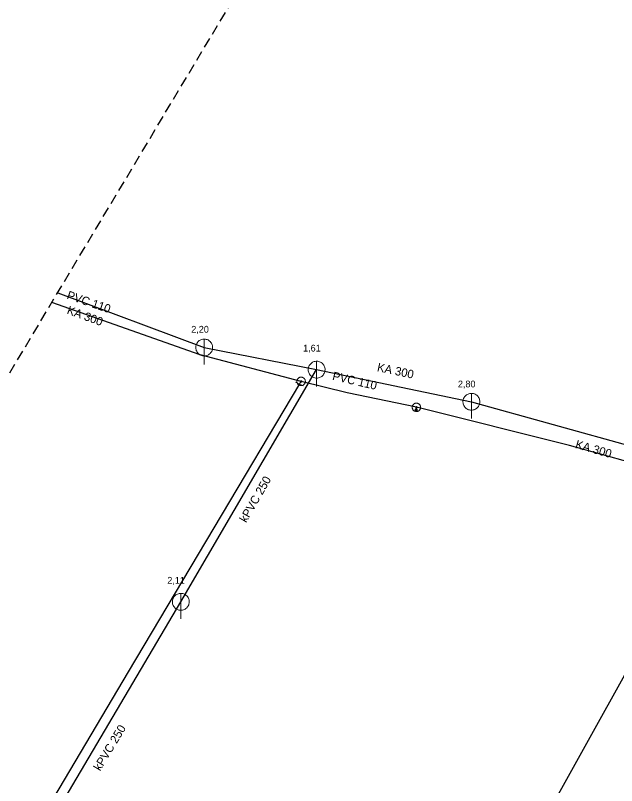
# Model space of a CAD drawing. Extents: x -724358 to -723714, y -973310 to -972026.
# Drawn here: x -724260.8 to -724189.5, y -973035.2 to -972943.8 of the extents above; entities that cross this region are included whole.
import ezdxf

# ---------------------------------------------------------------- set-up
doc = ezdxf.new("R2010")
doc.units = 0
doc.header["$LTSCALE"] = 0.4
doc.linetypes.add('MEDIUM_DASHED', pattern=[4.5, 3, -1.5])
for name, color, linetype, lineweight in [('1', 7, 'Continuous', 13), ('14', 7, 'Continuous', 13), ('17', 7, 'Continuous', 25), ('22', 7, 'Continuous', 13), ('34', 7, 'Continuous', 13), ('47', 7, 'Continuous', 13), ('9', 7, 'Continuous', 13)]:
    doc.layers.add(name, color=color, linetype=linetype, lineweight=lineweight)

msp = doc.modelspace()

# ---------------------------------------------------------------- linework, layer by layer
at = {"layer": '1', "linetype": 'MEDIUM_DASHED', "lineweight": 25}
msp.add_lwpolyline([(-723809.944, -972026.35), (-723713.647, -972034.723), (-723734.581, -972361.295), (-724123.956, -973039.561), (-724241.187, -973309.611), (-724358.418, -973148.418), (-723860.186, -972315.24)], close=True, dxfattribs=at)
at = {"layer": '14', "lineweight": 25}
for p, q in [((-724255.737, -972976.708), (-724238.37, -972983.21)), ((-724206.69, -972989.649), (-724175.35, -972998.37))]:
    msp.add_line(p, q, dxfattribs=at)
at = {"layer": '14'}
for p, q in [((-724226.875, -972987.23), (-724227.079, -972987.531)), ((-724213.21, -972990.309), (-724213.23, -972990.6))]:
    msp.add_line(p, q, dxfattribs=at)
at = {"layer": '14', "lineweight": 25}
for points in [[(-724199.68, -973042.18), (-724175.35, -972998.37), (-724168.649, -972968.05), (-724140.149, -972952.289), (-724129.112, -972956.537), (-724090.03, -972946.64), (-724084.339, -972950.81)], [(-724238.37, -972983.21), (-724225.039, -972985.84), (-724206.69, -972989.649)], [(-724259.629, -973044.75), (-724241.14, -973013.379), (-724225.039, -972985.84)]]:
    msp.add_lwpolyline(points, dxfattribs=at)
at = {"layer": '17'}
for points in [[(-724226.875, -972987.23), (-724238.85, -972984.07), (-724256.424, -972977.857)], [(-724213.21, -972990.309), (-724221.42, -972988.57), (-724226.875, -972987.23)], [(-724227.079, -972987.531), (-724247.38, -973021.691), (-724261.945, -973046.239), (-724298.824, -973108.59), (-724301.364, -973112.34), (-724301.535, -973112.48)], [(-724170.289, -973002.559), (-724176.69, -972999.98), (-724195.07, -972994.829), (-724213.21, -972990.309)]]:
    msp.add_lwpolyline(points, dxfattribs=at)
at = {"layer": '22'}
for p, q in [((-724238.37, -972985.21), (-724238.369, -972982.21)), ((-724225.039, -972987.84), (-724225.038, -972984.84)), ((-724206.69, -972991.649), (-724206.689, -972988.649)), ((-724241.14, -973015.379), (-724241.139, -973012.379))]:
    msp.add_line(p, q, dxfattribs=at)
for points in [[(-724237.37, -972983.21), (-724237.375, -972983.101), (-724237.393, -972982.993), (-724237.423, -972982.887), (-724237.463, -972982.786), (-724237.515, -972982.689), (-724237.577, -972982.599), (-724237.649, -972982.516), (-724237.729, -972982.442), (-724237.817, -972982.376), (-724237.911, -972982.321), (-724238.011, -972982.276), (-724238.116, -972982.243), (-724238.223, -972982.221), (-724238.332, -972982.211), (-724238.442, -972982.213), (-724238.55, -972982.227), (-724238.657, -972982.252), (-724238.76, -972982.289), (-724238.858, -972982.338), (-724238.95, -972982.396), (-724239.036, -972982.465), (-724239.113, -972982.542), (-724239.182, -972982.628), (-724239.241, -972982.72), (-724239.289, -972982.818), (-724239.326, -972982.921), (-724239.352, -972983.028), (-724239.366, -972983.136), (-724239.369, -972983.246), (-724239.359, -972983.355), (-724239.338, -972983.462), (-724239.304, -972983.566), (-724239.26, -972983.666), (-724239.205, -972983.761), (-724239.139, -972983.849), (-724239.065, -972983.929), (-724238.982, -972984.001), (-724238.892, -972984.063), (-724238.796, -972984.115), (-724238.694, -972984.156), (-724238.589, -972984.186), (-724238.481, -972984.204), (-724238.371, -972984.21), (-724238.262, -972984.204), (-724238.154, -972984.186), (-724238.049, -972984.157), (-724237.947, -972984.116), (-724237.85, -972984.064), (-724237.76, -972984.002), (-724237.677, -972983.931), (-724237.602, -972983.851), (-724237.537, -972983.763), (-724237.481, -972983.669), (-724237.437, -972983.569), (-724237.403, -972983.465), (-724237.381, -972983.357), (-724237.371, -972983.248)], [(-724224.039, -972985.84), (-724224.044, -972985.731), (-724224.062, -972985.623), (-724224.092, -972985.517), (-724224.132, -972985.416), (-724224.184, -972985.319), (-724224.246, -972985.229), (-724224.318, -972985.146), (-724224.398, -972985.072), (-724224.486, -972985.006), (-724224.58, -972984.951), (-724224.68, -972984.906), (-724224.785, -972984.873), (-724224.892, -972984.851), (-724225.001, -972984.841), (-724225.111, -972984.843), (-724225.219, -972984.857), (-724225.326, -972984.882), (-724225.429, -972984.919), (-724225.527, -972984.968), (-724225.619, -972985.026), (-724225.705, -972985.095), (-724225.782, -972985.172), (-724225.851, -972985.258), (-724225.91, -972985.35), (-724225.958, -972985.448), (-724225.995, -972985.551), (-724226.021, -972985.658), (-724226.035, -972985.766), (-724226.038, -972985.876), (-724226.028, -972985.985), (-724226.007, -972986.092), (-724225.973, -972986.196), (-724225.929, -972986.296), (-724225.874, -972986.391), (-724225.808, -972986.479), (-724225.734, -972986.559), (-724225.651, -972986.631), (-724225.561, -972986.693), (-724225.465, -972986.745), (-724225.363, -972986.786), (-724225.258, -972986.816), (-724225.15, -972986.834), (-724225.04, -972986.84), (-724224.931, -972986.834), (-724224.823, -972986.816), (-724224.718, -972986.787), (-724224.616, -972986.746), (-724224.519, -972986.694), (-724224.429, -972986.632), (-724224.346, -972986.561), (-724224.271, -972986.481), (-724224.206, -972986.393), (-724224.15, -972986.299), (-724224.106, -972986.199), (-724224.072, -972986.095), (-724224.05, -972985.987), (-724224.04, -972985.878)], [(-724205.69, -972989.649), (-724205.695, -972989.54), (-724205.713, -972989.432), (-724205.743, -972989.326), (-724205.783, -972989.225), (-724205.835, -972989.128), (-724205.897, -972989.038), (-724205.969, -972988.955), (-724206.049, -972988.881), (-724206.137, -972988.815), (-724206.231, -972988.76), (-724206.331, -972988.715), (-724206.436, -972988.682), (-724206.543, -972988.66), (-724206.652, -972988.65), (-724206.762, -972988.652), (-724206.87, -972988.666), (-724206.977, -972988.691), (-724207.08, -972988.728), (-724207.178, -972988.777), (-724207.27, -972988.835), (-724207.356, -972988.904), (-724207.433, -972988.981), (-724207.502, -972989.067), (-724207.561, -972989.159), (-724207.609, -972989.257), (-724207.646, -972989.36), (-724207.672, -972989.467), (-724207.686, -972989.575), (-724207.689, -972989.685), (-724207.679, -972989.794), (-724207.658, -972989.901), (-724207.624, -972990.005), (-724207.58, -972990.105), (-724207.525, -972990.2), (-724207.459, -972990.288), (-724207.385, -972990.368), (-724207.302, -972990.44), (-724207.212, -972990.502), (-724207.116, -972990.554), (-724207.014, -972990.595), (-724206.909, -972990.625), (-724206.801, -972990.643), (-724206.691, -972990.649), (-724206.582, -972990.643), (-724206.474, -972990.625), (-724206.369, -972990.596), (-724206.267, -972990.555), (-724206.17, -972990.503), (-724206.08, -972990.441), (-724205.997, -972990.37), (-724205.922, -972990.29), (-724205.857, -972990.202), (-724205.801, -972990.108), (-724205.757, -972990.008), (-724205.723, -972989.904), (-724205.701, -972989.796), (-724205.691, -972989.687)], [(-724240.14, -973013.379), (-724240.145, -973013.27), (-724240.163, -973013.162), (-724240.193, -973013.056), (-724240.233, -973012.955), (-724240.285, -973012.858), (-724240.347, -973012.768), (-724240.419, -973012.685), (-724240.499, -973012.611), (-724240.587, -973012.545), (-724240.681, -973012.49), (-724240.781, -973012.445), (-724240.886, -973012.412), (-724240.993, -973012.39), (-724241.102, -973012.38), (-724241.212, -973012.382), (-724241.32, -973012.396), (-724241.427, -973012.421), (-724241.53, -973012.458), (-724241.628, -973012.507), (-724241.72, -973012.565), (-724241.806, -973012.634), (-724241.883, -973012.711), (-724241.952, -973012.797), (-724242.011, -973012.889), (-724242.059, -973012.987), (-724242.096, -973013.09), (-724242.122, -973013.197), (-724242.136, -973013.305), (-724242.139, -973013.415), (-724242.129, -973013.524), (-724242.108, -973013.631), (-724242.074, -973013.735), (-724242.03, -973013.835), (-724241.975, -973013.93), (-724241.909, -973014.018), (-724241.835, -973014.098), (-724241.752, -973014.17), (-724241.662, -973014.232), (-724241.566, -973014.284), (-724241.464, -973014.325), (-724241.359, -973014.355), (-724241.251, -973014.373), (-724241.141, -973014.379), (-724241.032, -973014.373), (-724240.924, -973014.355), (-724240.819, -973014.326), (-724240.717, -973014.285), (-724240.62, -973014.233), (-724240.53, -973014.171), (-724240.447, -973014.1), (-724240.372, -973014.02), (-724240.307, -973013.932), (-724240.251, -973013.838), (-724240.207, -973013.738), (-724240.173, -973013.634), (-724240.151, -973013.526), (-724240.141, -973013.417)]]:
    msp.add_lwpolyline(points, close=True, dxfattribs=at)
at = {"layer": '34'}
msp.add_line((-724226.628, -972987.748), (-724227.528, -972987.312), dxfattribs=at)
at = {"layer": '47'}
for points in [[(-724227.36, -972987.11), (-724227.37, -972987.161), (-724227.374, -972987.214), (-724227.373, -972987.266), (-724227.367, -972987.318), (-724227.355, -972987.369), (-724227.337, -972987.419), (-724227.314, -972987.465), (-724227.287, -972987.51), (-724227.256, -972987.552), (-724227.221, -972987.59), (-724227.181, -972987.625), (-724227.137, -972987.654), (-724227.092, -972987.68), (-724227.044, -972987.7), (-724226.994, -972987.715), (-724226.943, -972987.725), (-724226.89, -972987.729), (-724226.837, -972987.728), (-724226.786, -972987.722), (-724226.735, -972987.71), (-724226.685, -972987.692), (-724226.638, -972987.67), (-724226.593, -972987.643), (-724226.551, -972987.612), (-724226.514, -972987.576), (-724226.479, -972987.536), (-724226.449, -972987.493), (-724226.424, -972987.447), (-724226.404, -972987.399), (-724226.389, -972987.349), (-724226.379, -972987.298), (-724226.375, -972987.245), (-724226.375, -972987.193), (-724226.382, -972987.141), (-724226.394, -972987.09), (-724226.411, -972987.041), (-724226.433, -972986.993), (-724226.46, -972986.948), (-724226.492, -972986.906), (-724226.528, -972986.869), (-724226.568, -972986.834), (-724226.61, -972986.804), (-724226.657, -972986.779), (-724226.705, -972986.759), (-724226.755, -972986.744), (-724226.806, -972986.734), (-724226.859, -972986.73), (-724226.911, -972986.731), (-724226.963, -972986.737), (-724227.014, -972986.749), (-724227.063, -972986.766), (-724227.11, -972986.789), (-724227.155, -972986.816), (-724227.197, -972986.848), (-724227.235, -972986.883), (-724227.27, -972986.923), (-724227.299, -972986.966), (-724227.325, -972987.012), (-724227.345, -972987.06)], [(-724226.954, -972987.21), (-724226.956, -972987.219), (-724226.956, -972987.227), (-724226.956, -972987.235), (-724226.955, -972987.244), (-724226.953, -972987.252), (-724226.95, -972987.26), (-724226.947, -972987.268), (-724226.942, -972987.276), (-724226.937, -972987.282), (-724226.931, -972987.289), (-724226.924, -972987.294), (-724226.917, -972987.299), (-724226.91, -972987.303), (-724226.903, -972987.307), (-724226.894, -972987.309), (-724226.885, -972987.311), (-724226.877, -972987.311), (-724226.869, -972987.311), (-724226.86, -972987.31), (-724226.852, -972987.308), (-724226.844, -972987.305), (-724226.836, -972987.302), (-724226.828, -972987.297), (-724226.821, -972987.292), (-724226.815, -972987.286), (-724226.81, -972987.279), (-724226.805, -972987.272), (-724226.801, -972987.265), (-724226.797, -972987.258), (-724226.795, -972987.249), (-724226.793, -972987.24), (-724226.793, -972987.232), (-724226.793, -972987.224), (-724226.794, -972987.215), (-724226.796, -972987.207), (-724226.798, -972987.199), (-724226.802, -972987.191), (-724226.807, -972987.183), (-724226.812, -972987.176), (-724226.818, -972987.17), (-724226.825, -972987.165), (-724226.832, -972987.16), (-724226.839, -972987.156), (-724226.846, -972987.152), (-724226.855, -972987.15), (-724226.864, -972987.148), (-724226.872, -972987.148), (-724226.88, -972987.148), (-724226.889, -972987.149), (-724226.897, -972987.151), (-724226.905, -972987.153), (-724226.913, -972987.157), (-724226.921, -972987.162), (-724226.927, -972987.167), (-724226.934, -972987.173), (-724226.939, -972987.18), (-724226.944, -972987.187), (-724226.948, -972987.194), (-724226.952, -972987.201)], [(-724212.714, -972990.375), (-724212.71, -972990.323), (-724212.711, -972990.27), (-724212.718, -972990.219), (-724212.73, -972990.168), (-724212.747, -972990.118), (-724212.77, -972990.07), (-724212.798, -972990.026), (-724212.829, -972989.985), (-724212.865, -972989.947), (-724212.904, -972989.912), (-724212.948, -972989.882), (-724212.994, -972989.858), (-724213.042, -972989.838), (-724213.092, -972989.823), (-724213.143, -972989.813), (-724213.195, -972989.809), (-724213.248, -972989.81), (-724213.3, -972989.817), (-724213.35, -972989.829), (-724213.4, -972989.846), (-724213.448, -972989.869), (-724213.493, -972989.896), (-724213.534, -972989.928), (-724213.572, -972989.964), (-724213.606, -972990.003), (-724213.636, -972990.047), (-724213.661, -972990.093), (-724213.68, -972990.141), (-724213.695, -972990.191), (-724213.705, -972990.242), (-724213.709, -972990.294), (-724213.708, -972990.347), (-724213.702, -972990.399), (-724213.689, -972990.449), (-724213.672, -972990.499), (-724213.65, -972990.546), (-724213.623, -972990.591), (-724213.591, -972990.633), (-724213.554, -972990.671), (-724213.515, -972990.705), (-724213.471, -972990.735), (-724213.426, -972990.76), (-724213.377, -972990.779), (-724213.327, -972990.794), (-724213.276, -972990.804), (-724213.224, -972990.808), (-724213.171, -972990.807), (-724213.12, -972990.801), (-724213.069, -972990.788), (-724213.019, -972990.771), (-724212.972, -972990.749), (-724212.928, -972990.721), (-724212.886, -972990.69), (-724212.848, -972990.653), (-724212.813, -972990.614), (-724212.783, -972990.57), (-724212.759, -972990.525), (-724212.739, -972990.476), (-724212.724, -972990.426)], [(-724213.128, -972990.319), (-724213.127, -972990.31), (-724213.128, -972990.302), (-724213.129, -972990.294), (-724213.131, -972990.286), (-724213.134, -972990.277), (-724213.138, -972990.27), (-724213.142, -972990.262), (-724213.147, -972990.255), (-724213.153, -972990.249), (-724213.159, -972990.244), (-724213.167, -972990.239), (-724213.174, -972990.234), (-724213.182, -972990.231), (-724213.19, -972990.228), (-724213.199, -972990.227), (-724213.208, -972990.226), (-724213.216, -972990.227), (-724213.224, -972990.228), (-724213.232, -972990.23), (-724213.241, -972990.233), (-724213.248, -972990.237), (-724213.256, -972990.241), (-724213.263, -972990.246), (-724213.27, -972990.252), (-724213.274, -972990.258), (-724213.279, -972990.266), (-724213.284, -972990.273), (-724213.287, -972990.281), (-724213.29, -972990.289), (-724213.291, -972990.298), (-724213.292, -972990.307), (-724213.291, -972990.315), (-724213.29, -972990.323), (-724213.288, -972990.331), (-724213.285, -972990.34), (-724213.282, -972990.347), (-724213.277, -972990.355), (-724213.272, -972990.362), (-724213.266, -972990.369), (-724213.26, -972990.373), (-724213.252, -972990.378), (-724213.245, -972990.383), (-724213.237, -972990.386), (-724213.229, -972990.389), (-724213.22, -972990.39), (-724213.211, -972990.391), (-724213.203, -972990.39), (-724213.195, -972990.389), (-724213.187, -972990.387), (-724213.178, -972990.384), (-724213.171, -972990.381), (-724213.163, -972990.376), (-724213.156, -972990.371), (-724213.15, -972990.365), (-724213.145, -972990.359), (-724213.14, -972990.351), (-724213.135, -972990.344), (-724213.132, -972990.336), (-724213.129, -972990.328)]]:
    msp.add_lwpolyline(points, close=True, dxfattribs=at)
at = {"layer": '9'}
for points in [[(-724213.356, -972990.6), (-724213.356, -972990.613), (-724213.353, -972990.626), (-724213.351, -972990.639), (-724213.346, -972990.651), (-724213.34, -972990.663), (-724213.333, -972990.674), (-724213.325, -972990.684), (-724213.315, -972990.694), (-724213.304, -972990.702), (-724213.294, -972990.709), (-724213.282, -972990.715), (-724213.27, -972990.72), (-724213.257, -972990.723), (-724213.244, -972990.725), (-724213.231, -972990.727), (-724213.218, -972990.726), (-724213.205, -972990.724), (-724213.192, -972990.721), (-724213.179, -972990.716), (-724213.168, -972990.71), (-724213.157, -972990.703), (-724213.147, -972990.695), (-724213.137, -972990.685), (-724213.129, -972990.675), (-724213.122, -972990.664), (-724213.116, -972990.652), (-724213.111, -972990.64), (-724213.108, -972990.627), (-724213.106, -972990.614), (-724213.103, -972990.601), (-724213.105, -972990.588), (-724213.107, -972990.575), (-724213.11, -972990.562), (-724213.115, -972990.55), (-724213.12, -972990.538), (-724213.128, -972990.527), (-724213.136, -972990.517), (-724213.146, -972990.507), (-724213.156, -972990.499), (-724213.167, -972990.492), (-724213.179, -972990.486), (-724213.191, -972990.481), (-724213.204, -972990.478), (-724213.217, -972990.476), (-724213.23, -972990.475), (-724213.243, -972990.475), (-724213.255, -972990.477), (-724213.269, -972990.48), (-724213.281, -972990.485), (-724213.293, -972990.491), (-724213.304, -972990.498), (-724213.314, -972990.506), (-724213.324, -972990.516), (-724213.331, -972990.526), (-724213.339, -972990.537), (-724213.345, -972990.549), (-724213.35, -972990.561), (-724213.353, -972990.574), (-724213.355, -972990.587)], [(-724213.336, -972990.6), (-724213.337, -972990.611), (-724213.335, -972990.622), (-724213.331, -972990.633), (-724213.328, -972990.643), (-724213.323, -972990.653), (-724213.317, -972990.662), (-724213.309, -972990.671), (-724213.302, -972990.679), (-724213.293, -972990.686), (-724213.284, -972990.692), (-724213.274, -972990.697), (-724213.264, -972990.701), (-724213.253, -972990.704), (-724213.242, -972990.707), (-724213.231, -972990.707), (-724213.22, -972990.707), (-724213.209, -972990.705), (-724213.198, -972990.702), (-724213.188, -972990.698), (-724213.178, -972990.693), (-724213.169, -972990.687), (-724213.16, -972990.68), (-724213.152, -972990.672), (-724213.145, -972990.663), (-724213.139, -972990.654), (-724213.134, -972990.644), (-724213.13, -972990.634), (-724213.127, -972990.623), (-724213.125, -972990.612), (-724213.124, -972990.601), (-724213.124, -972990.59), (-724213.125, -972990.579), (-724213.129, -972990.568), (-724213.133, -972990.558), (-724213.138, -972990.548), (-724213.144, -972990.539), (-724213.151, -972990.53), (-724213.159, -972990.522), (-724213.168, -972990.515), (-724213.177, -972990.509), (-724213.187, -972990.504), (-724213.196, -972990.5), (-724213.208, -972990.497), (-724213.218, -972990.495), (-724213.23, -972990.495), (-724213.241, -972990.494), (-724213.252, -972990.496), (-724213.263, -972990.499), (-724213.272, -972990.503), (-724213.282, -972990.508), (-724213.292, -972990.514), (-724213.301, -972990.521), (-724213.309, -972990.529), (-724213.316, -972990.538), (-724213.321, -972990.547), (-724213.326, -972990.557), (-724213.331, -972990.567), (-724213.334, -972990.578), (-724213.336, -972990.589)], [(-724213.317, -972990.6), (-724213.317, -972990.609), (-724213.316, -972990.618), (-724213.313, -972990.627), (-724213.309, -972990.635), (-724213.306, -972990.643), (-724213.301, -972990.651), (-724213.294, -972990.658), (-724213.289, -972990.664), (-724213.282, -972990.67), (-724213.274, -972990.675), (-724213.266, -972990.679), (-724213.258, -972990.682), (-724213.249, -972990.685), (-724213.24, -972990.686), (-724213.231, -972990.688), (-724213.222, -972990.687), (-724213.213, -972990.686), (-724213.204, -972990.683), (-724213.196, -972990.68), (-724213.188, -972990.676), (-724213.179, -972990.671), (-724213.173, -972990.665), (-724213.167, -972990.659), (-724213.161, -972990.652), (-724213.156, -972990.644), (-724213.152, -972990.636), (-724213.149, -972990.628), (-724213.146, -972990.619), (-724213.145, -972990.61), (-724213.142, -972990.601), (-724213.144, -972990.592), (-724213.145, -972990.583), (-724213.147, -972990.574), (-724213.151, -972990.566), (-724213.155, -972990.558), (-724213.16, -972990.55), (-724213.166, -972990.543), (-724213.172, -972990.537), (-724213.179, -972990.531), (-724213.187, -972990.526), (-724213.195, -972990.522), (-724213.203, -972990.519), (-724213.212, -972990.516), (-724213.221, -972990.515), (-724213.23, -972990.514), (-724213.239, -972990.514), (-724213.248, -972990.515), (-724213.257, -972990.518), (-724213.265, -972990.521), (-724213.272, -972990.525), (-724213.281, -972990.53), (-724213.288, -972990.536), (-724213.294, -972990.542), (-724213.299, -972990.549), (-724213.304, -972990.557), (-724213.309, -972990.565), (-724213.312, -972990.573), (-724213.315, -972990.582), (-724213.316, -972990.591)], [(-724213.297, -972990.6), (-724213.297, -972990.607), (-724213.296, -972990.614), (-724213.294, -972990.621), (-724213.292, -972990.627), (-724213.289, -972990.633), (-724213.285, -972990.639), (-724213.281, -972990.645), (-724213.276, -972990.65), (-724213.27, -972990.654), (-724213.264, -972990.658), (-724213.258, -972990.661), (-724213.252, -972990.664), (-724213.245, -972990.665), (-724213.238, -972990.668), (-724213.231, -972990.668), (-724213.223, -972990.668), (-724213.217, -972990.666), (-724213.21, -972990.665), (-724213.204, -972990.662), (-724213.196, -972990.659), (-724213.192, -972990.655), (-724213.186, -972990.651), (-724213.181, -972990.646), (-724213.177, -972990.64), (-724213.173, -972990.634), (-724213.169, -972990.628), (-724213.167, -972990.622), (-724213.165, -972990.615), (-724213.164, -972990.608), (-724213.163, -972990.601), (-724213.163, -972990.594), (-724213.164, -972990.587), (-724213.166, -972990.58), (-724213.169, -972990.574), (-724213.172, -972990.567), (-724213.176, -972990.562), (-724213.179, -972990.556), (-724213.184, -972990.551), (-724213.191, -972990.547), (-724213.196, -972990.543), (-724213.203, -972990.54), (-724213.209, -972990.537), (-724213.216, -972990.535), (-724213.223, -972990.534), (-724213.23, -972990.534), (-724213.237, -972990.534), (-724213.244, -972990.534), (-724213.25, -972990.536), (-724213.257, -972990.539), (-724213.263, -972990.542), (-724213.269, -972990.546), (-724213.275, -972990.55), (-724213.28, -972990.555), (-724213.284, -972990.561), (-724213.288, -972990.566), (-724213.291, -972990.573), (-724213.294, -972990.579), (-724213.294, -972990.586), (-724213.297, -972990.593)], [(-724213.277, -972990.6), (-724213.277, -972990.605), (-724213.277, -972990.61), (-724213.276, -972990.615), (-724213.274, -972990.619), (-724213.272, -972990.624), (-724213.269, -972990.628), (-724213.266, -972990.631), (-724213.262, -972990.635), (-724213.259, -972990.638), (-724213.255, -972990.641), (-724213.25, -972990.643), (-724213.245, -972990.645), (-724213.241, -972990.646), (-724213.236, -972990.648), (-724213.231, -972990.648), (-724213.226, -972990.648), (-724213.221, -972990.647), (-724213.216, -972990.646), (-724213.212, -972990.644), (-724213.206, -972990.642), (-724213.203, -972990.639), (-724213.199, -972990.636), (-724213.196, -972990.632), (-724213.193, -972990.629), (-724213.19, -972990.625), (-724213.188, -972990.62), (-724213.186, -972990.616), (-724213.184, -972990.611), (-724213.184, -972990.606), (-724213.183, -972990.601), (-724213.183, -972990.596), (-724213.184, -972990.591), (-724213.184, -972990.586), (-724213.187, -972990.582), (-724213.189, -972990.577), (-724213.192, -972990.573), (-724213.195, -972990.569), (-724213.198, -972990.566), (-724213.201, -972990.563), (-724213.206, -972990.56), (-724213.211, -972990.558), (-724213.215, -972990.556), (-724213.22, -972990.555), (-724213.225, -972990.554), (-724213.23, -972990.554), (-724213.235, -972990.554), (-724213.24, -972990.555), (-724213.245, -972990.555), (-724213.249, -972990.557), (-724213.254, -972990.559), (-724213.258, -972990.562), (-724213.261, -972990.565), (-724213.265, -972990.568), (-724213.267, -972990.572), (-724213.271, -972990.576), (-724213.272, -972990.581), (-724213.275, -972990.585), (-724213.276, -972990.59), (-724213.277, -972990.595)], [(-724213.257, -972990.6), (-724213.257, -972990.603), (-724213.258, -972990.606), (-724213.257, -972990.608), (-724213.255, -972990.611), (-724213.255, -972990.614), (-724213.253, -972990.616), (-724213.25, -972990.618), (-724213.249, -972990.62), (-724213.247, -972990.622), (-724213.245, -972990.624), (-724213.242, -972990.626), (-724213.239, -972990.627), (-724213.237, -972990.627), (-724213.233, -972990.628), (-724213.231, -972990.628), (-724213.228, -972990.628), (-724213.225, -972990.628), (-724213.222, -972990.627), (-724213.22, -972990.626), (-724213.217, -972990.625), (-724213.215, -972990.623), (-724213.212, -972990.621), (-724213.21, -972990.619), (-724213.209, -972990.617), (-724213.206, -972990.615), (-724213.206, -972990.612), (-724213.204, -972990.609), (-724213.204, -972990.607), (-724213.203, -972990.604), (-724213.201, -972990.601), (-724213.203, -972990.598), (-724213.203, -972990.595), (-724213.204, -972990.592), (-724213.205, -972990.59), (-724213.206, -972990.587), (-724213.208, -972990.585), (-724213.209, -972990.582), (-724213.211, -972990.58), (-724213.214, -972990.579), (-724213.216, -972990.577), (-724213.218, -972990.576), (-724213.221, -972990.575), (-724213.223, -972990.574), (-724213.227, -972990.574), (-724213.23, -972990.573), (-724213.233, -972990.574), (-724213.236, -972990.573), (-724213.238, -972990.575), (-724213.241, -972990.575), (-724213.244, -972990.576), (-724213.245, -972990.578), (-724213.248, -972990.579), (-724213.25, -972990.581), (-724213.252, -972990.584), (-724213.254, -972990.586), (-724213.255, -972990.589), (-724213.255, -972990.591), (-724213.257, -972990.594), (-724213.257, -972990.597)], [(-724213.238, -972990.6), (-724213.238, -972990.602), (-724213.238, -972990.602), (-724213.237, -972990.602), (-724213.237, -972990.604), (-724213.238, -972990.605), (-724213.236, -972990.605), (-724213.236, -972990.605), (-724213.236, -972990.607), (-724213.236, -972990.607), (-724213.235, -972990.608), (-724213.233, -972990.608), (-724213.233, -972990.608), (-724213.233, -972990.609), (-724213.231, -972990.609), (-724213.231, -972990.609), (-724213.23, -972990.609), (-724213.228, -972990.609), (-724213.228, -972990.608), (-724213.228, -972990.608), (-724213.226, -972990.608), (-724213.226, -972990.607), (-724213.226, -972990.607), (-724213.225, -972990.606), (-724213.225, -972990.606), (-724213.223, -972990.605), (-724213.223, -972990.604), (-724213.222, -972990.603), (-724213.222, -972990.603), (-724213.222, -972990.602), (-724213.222, -972990.601), (-724213.222, -972990.6), (-724213.222, -972990.599), (-724213.222, -972990.599), (-724213.223, -972990.598), (-724213.223, -972990.597), (-724213.223, -972990.596), (-724213.223, -972990.596), (-724213.225, -972990.595), (-724213.225, -972990.595), (-724213.226, -972990.594), (-724213.227, -972990.594), (-724213.228, -972990.593), (-724213.228, -972990.593), (-724213.228, -972990.593), (-724213.23, -972990.593), (-724213.231, -972990.593), (-724213.232, -972990.593), (-724213.232, -972990.593), (-724213.233, -972990.594), (-724213.233, -972990.593), (-724213.235, -972990.595), (-724213.235, -972990.595), (-724213.236, -972990.595), (-724213.236, -972990.595), (-724213.237, -972990.597), (-724213.237, -972990.598), (-724213.237, -972990.599), (-724213.238, -972990.599), (-724213.238, -972990.6)]]:
    msp.add_lwpolyline(points, close=True, dxfattribs=at)

# ---------------------------------------------------------------- texts
at = {"layer": '1'}
for s, rotation, p in [('PVC 110 ', 341, (-724254.735, -972977.408)), ('KA 300', 340, (-724254.728, -972979.176)), ('KA 300', 348, (-724217.93, -972986.003)), ('PVC 110 ', 347, (-724223.239, -972987.038)), ('KA 300', 344, (-724194.442, -972995.117)), ('kPVC 250', 60, (-724233.394, -973004.064)), ('kPVC 250', 59, (-724250.705, -973033.518))]:
    msp.add_text(s, height=1, rotation=rotation, dxfattribs=at).set_placement(p)
for s, p in [('2,20', (-724239.9, -972981.448)), ('1,61', (-724226.639, -972983.687)), ('2,80', (-724208.289, -972987.938)), ('2,11', (-724242.74, -973011.227))]:
    msp.add_text(s, height=0.8, dxfattribs=at).set_placement(p)

doc.saveas('drawing.dxf')
